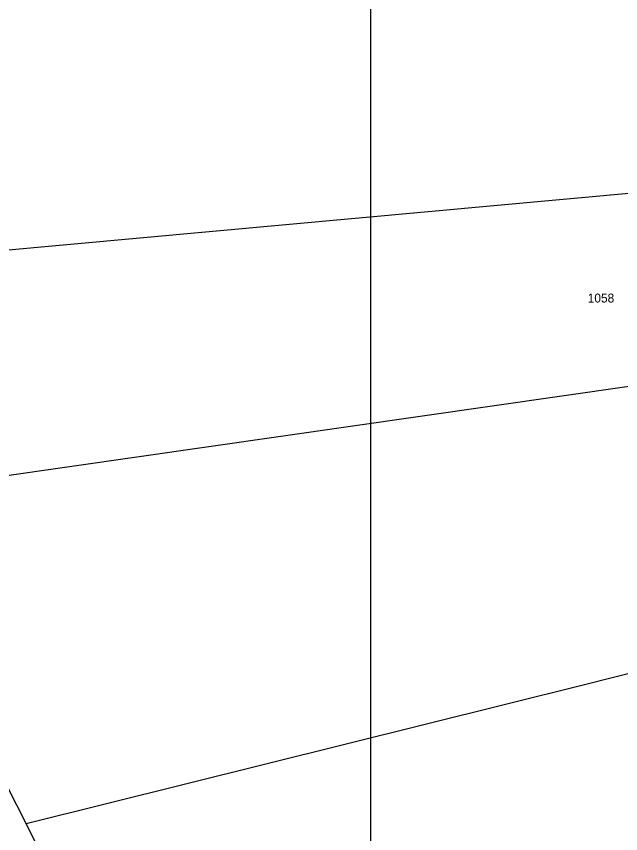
# Model space of a CAD drawing. Extents: x -604848 to -603227, y -1111879 to -1109838.
# Drawn here: x -603888.8 to -603773.6, y -1110343.6 to -1110187.8 of the extents above; entities that cross this region are included whole.
import ezdxf

# ---------------------------------------------------------------- set-up
doc = ezdxf.new("R2010")
doc.units = 0
for name, color, linetype in [('1', 7, 'Continuous'), ('14', 7, 'Continuous'), ('7', 7, 'Continuous')]:
    doc.layers.add(name, color=color, linetype=linetype)

msp = doc.modelspace()

# ---------------------------------------------------------------- linework, layer by layer
at = {"layer": '1'}
for p, q in [((-603943.43, -1110237.19), (-603748.02, -1110219.29)), ((-603918.81, -1110279.39), (-603771.57, -1110258.26)), ((-603918.81, -1110279.39), (-603886.88, -1110341.74)), ((-603674.17, -1110288.7), (-603780.53, -1110315.22)), ((-603780.53, -1110315.22), (-603886.88, -1110341.74)), ((-603886.88, -1110341.74), (-603842.93, -1110429.54))]:
    msp.add_line(p, q, dxfattribs=at)
msp.add_lwpolyline([(-603227.31, -1110677.93), (-603227.31, -1109837.93), (-603821.31, -1109837.93), (-603821.31, -1110677.93), (-603227.31, -1110677.93)], dxfattribs=at)
at = {"layer": '7'}
for points in [[(-603832.97, -1110433.54), (-603835.87, -1110430.45), (-603838.77, -1110427.36), (-603841.67, -1110424.27), (-603847.26, -1110418.31), (-603853.48, -1110412.94), (-603859.43, -1110407.36), (-603865.68, -1110401.5), (-603873.96, -1110398.15), (-603879.7, -1110391.45), (-603886.92, -1110383.01), (-603882.86, -1110369.76), (-603887.08, -1110359.85), (-603893.83, -1110344.03), (-603899.3, -1110326.95), (-603910.93, -1110313.84), (-603919.05, -1110304.7), (-603927.68, -1110296.49), (-603936.23, -1110288.01), (-603942.66, -1110281.65), (-603949.71, -1110275.91), (-603956.03, -1110269.41), (-603962.97, -1110262.28), (-603958.28, -1110248.85), (-603963.99, -1110240.66), (-603968.51, -1110234.18), (-603973.41, -1110227.7), (-603979.81, -1110223.11), (-603983.65, -1110220.36), (-603987.5, -1110217.6), (-603991.34, -1110214.85)], [(-603847.4, -1110438.23), (-603849.93, -1110435.65), (-603852.46, -1110433.06), (-603854.99, -1110430.47), (-603859.22, -1110426.15), (-603863.16, -1110421.54), (-603867.31, -1110417.14), (-603872.27, -1110411.88), (-603879.33, -1110409.19), (-603884.37, -1110403.69), (-603891.25, -1110396.18), (-603895.06, -1110386.94), (-603898.56, -1110377.63), (-603902.93, -1110366.04), (-603901.59, -1110352.93), (-603906.69, -1110341.58), (-603910.59, -1110332.9), (-603915.37, -1110324.38), (-603922.34, -1110318.03), (-603928.71, -1110312.22), (-603935.08, -1110306.41), (-603941.45, -1110300.6)]]:
    msp.add_open_spline(points, degree=3, dxfattribs=at)

# ---------------------------------------------------------------- texts
at = {"layer": '14'}
msp.add_text('1058', height=1.7, dxfattribs=at).set_placement((-603779.9, -1110242.35))

doc.saveas('drawing.dxf')
